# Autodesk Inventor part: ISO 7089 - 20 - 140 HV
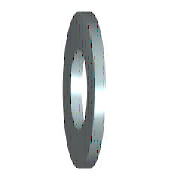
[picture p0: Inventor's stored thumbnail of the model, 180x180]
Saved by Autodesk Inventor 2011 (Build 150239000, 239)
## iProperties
IsCustomPart: 0
Created: 2009-02
Part Number: ISO 7089 - 20 - 140 HV
Material: Stainless Steel
Description: Plain washers - Normal series - Product grade A
Document SubType Name: Modeling
Standard: ISO 7089
Designer: V.de Jong
Standard Revision: Second edition 2000-06-01
Standards Organization: ISO
Language: en-US
Size Designation: 20 - 140 HV
Categories: <MemberInstance><Categories><Category DisplayName="Fasteners" InternalName="e4da775c-781d-43d5-af7c-5136215cf5a6" Mnemonic="FSTN"><Category DisplayName="Washers
Density: 8.08 g/cm^3
Mass: 17.6673 g
Surface Area: 20.0434 cm^2
Volume: 2.18655 cm^3
Author: V.de Jong
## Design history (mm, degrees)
body "Solid1"
sketch "Sketch"
  geometry: C1 r 18.5 at (0, 0); C2 r 10.5 at (0, 0); 1 further point
  constraints: 2 centre point, 2 coincident
  dimensions: "d0" = 21 diameter of C2 (= SD1); "d1" = 37 diameter of C1 (= SD2)
extrude "Body" new body sketch "Sketch" distance "d2" = 3 (= SD); taper "d3" = 0 deg
workaxis "Work Axis1"
workplane "Work Plane1"
other parameters: "SD1" = 21 [user parameter; used in 1 equation term], "SD2" = 37 [user parameter; used in 1 equation term], "SD" = 3 [user parameter; used in 1 equation term], "d4" = 0, "d5" = 0, "d6" = 0, "d7" = 0
